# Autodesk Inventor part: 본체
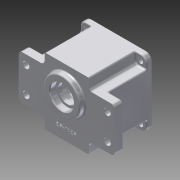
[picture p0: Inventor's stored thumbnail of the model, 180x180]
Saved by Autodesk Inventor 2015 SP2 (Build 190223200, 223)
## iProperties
Created: 2015-06
Part Number: 본체
Material: 알루미늄 6061
Document SubType Name: Modeling
Designer: AMC
Density: 2.7 g/cm^3
Appearance: 알루미늄 - 평지
Mass: 702.679 g
Surface Area: 673.039 cm^2
Volume: 260.252 cm^3
Author: AMC
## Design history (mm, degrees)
sketch "스케치1"
  geometry: L1 (-45, 45)-(45, 45); L2 (45, 45)-(45, -45); L3 (45, -45)-(-45, -45); L4 (-45, -45)-(-45, 45); 3 further points
  constraints: 8 end point, 2 midpoint, 2 parallel, 2 perpendicular, 1 horizontal, 1 horizontal alignment, 1 vertical alignment
  dimensions: "d0" = 90 distance of L1.start L1.end
extrude "돌출1" new body sketch "스케치1" distance "d1" = 70; taper "d2" = 0 deg
sketch "스케치2"
  geometry: L1 (-65, 30)-(65, 30); L2 (65, 30)-(65, -30); L3 (65, -30)-(-65, -30); L4 (-65, -30)-(-65, 30); 3 further points
  constraints: 8 end point, 2 midpoint, 2 parallel, 1 horizontal, 1 horizontal alignment, 1 perpendicular, 1 vertical alignment
  dimensions: "d3" = 60 distance of L3.end L1.start; "d4" = 130 distance of L1.start L1.end
extrude "돌출2" join sketch "스케치2" distance "d5" = 12; taper "d6" = 0 deg
sketch "스케치3"
  geometry: 2 further points
  constraints: 1 coincident
hole "구멍1" sketch "스케치3" at (0, 0) diameter "d7" = 78; stored, may be unused: countersink angle "d11" = 90 deg, drill point angle "d13" = 0 deg; dims "d8" = 6, "d9" = 80, "d10" = 9, "d12" = 61
sketch "스케치4"
  geometry: L1 (65, -30)-(45, -30) reference; L2 (45, -30)-(45, -45) reference; L3 (45, -45)-(-45, -45) reference; L4 (-45, -45)-(-45, -30) reference; L5 (-45, -30)-(-65, -30) reference; L6 (-65, -30)-(-65, 30) reference; L7 (-65, 30)-(-45, 30) reference; L8 (-45, 30)-(-45, 45) reference; L9 (-45, 45)-(45, 45) reference; L10 (45, 45)-(45, 30) reference; L11 (45, 30)-(65, 30) reference; L12 (65, 30)-(65, -30) reference; L13 (-45, 45)-(-30, 45); L14 (-30, 45)-(-30, 30); L15 (-30, 30)-(-45, 30); L16 (-45, 30)-(-45, 45); L17 (45, 45)-(30, 45); L18 (30, 45)-(30, 30); L19 (30, 30)-(45, 30); L20 (45, 30)-(45, 45); L21 (-45, -45)-(-30, -45); L22 (-30, -45)-(-30, -30); L23 (-30, -30)-(-45, -30); L24 (-45, -30)-(-45, -45); L25 (45, -45)-(30, -45); L26 (30, -45)-(30, -30); L27 (30, -30)-(45, -30); L28 (45, -30)-(45, -45); 1 further point
  constraints: 32 end point, 8 parallel, 5 equal length, 4 horizontal, 4 perpendicular
  dimensions: "d14" = 60 distance between parallel lines of L18 L14; "d15" = 60 distance between parallel lines of L23 L15; "d16" = 60 distance between parallel lines of L26 L22
extrude "돌출3" cut sketch "스케치4" distance "d17" = 63; taper "d18" = 0 deg
fillet "모깎기1" dims "d19" = 5
fillet "모깎기2" dims "d20" = 8
sketch "스케치5"
  geometry: C1 r 25 at (0, 11); 1 further point
  constraints: 1 centre point, 1 vertical alignment
  dimensions: "d21" = 11 distance of point (0, 0) C1.centre; "d22" = 50 diameter of C1
extrude "돌출4" join sketch "스케치5" distance "d23" = 7; taper "d24" = 0 deg
sketch "스케치6"
  geometry: C1 r 20.5 at (0, 11); C2 r 14 at (0, -20); 1 further point
  constraints: 2 centre point, 2 vertical alignment
  dimensions: "d25" = 11 distance of point (0, 0) C1.centre; "d26" = 20 distance of C2.centre point (0, 0); "d27" = 41 diameter of C1; "d28" = 28 diameter of C2
extrude "돌출5" join sketch "스케치6" distance "d29" = 7; taper "d30" = 0 deg
hole "구멍2" diameter "d33" = 25; stored, may be unused: countersink angle "d37" = 90 deg, drill point angle "d39" = 0 deg; dims "d31" = 10, "d32" = 10, "d34" = 6, "d35" = 32, "d36" = 8, "d38" = 61
hole "구멍3" diameter "d42" = 25; stored, may be unused: countersink angle "d46" = 90 deg, drill point angle "d48" = 0 deg; dims "d40" = 10, "d41" = 10, "d43" = 6, "d44" = 35, "d45" = 10, "d47" = 61
hole "구멍4" diameter "d51" = 19; stored, may be unused: countersink angle "d55" = 90 deg, drill point angle "d57" = 0 deg; dims "d49" = 10, "d50" = 10, "d52" = 6, "d53" = 22, "d54" = 7, "d56" = 8
fillet "모깎기3" dims "d58" = 2
fillet "모깎기4" dims "d59" = 2
fillet "모깎기5" dims "d60" = 2
fillet "모깎기8" dims "d63" = 2
fillet "모깎기9" dims "d64" = 2
fillet "모깎기10" dims "d65" = 2
fillet "모깎기11" dims "d66" = 2
chamfer "모따기1" distance "d67" = 1; stored, may be unused: second distance "d68" = 2, angle "d69" = 45 deg
chamfer "모따기2" distance "d70" = 1; stored, may be unused: second distance "d71" = 2, angle "d72" = 45 deg
fillet "모깎기12" dims "d73" = 2
sketch "스케치7"
  geometry: L1 (-28, 45)-(28, 45) reference; L2 (30, 43)-(30, 35) reference; L3 (35, 30)-(43, 30) reference; L4 (45, 28)-(45, -28) reference; L5 (43, -30)-(35, -30) reference; L6 (30, -35)-(30, -43) reference; L7 (28, -45)-(-28, -45) reference; L8 (-30, -43)-(-30, -35) reference; L9 (-35, -30)-(-43, -30) reference; L10 (-45, -28)-(-45, 28) reference; L11 (-43, 30)-(-35, 30) reference; L12 (-30, 35)-(-30, 43) reference; L13 (0, 0)-(-39, 0); L14 (0, 0)-(-24.749, 24.749); L15 (-27.577, 21.92)-(-30.26, 24.603); L16 (-21.92, 27.577)-(-24.603, 30.26); C1 r 40 at (0, 0) reference; A1 r 2 centre (-28, 43) between (-28, 45) and (-30, 43) reference; A2 r 2 centre (28, 43) between (30, 43) and (28, 45) reference; A3 r 5 centre (35, 35) between (30, 35) and (35, 30) reference; A4 r 2 centre (43, 28) between (45, 28) and (43, 30) reference; A5 r 2 centre (43, -28) between (43, -30) and (45, -28) reference; A6 r 5 centre (35, -35) between (35, -30) and (30, -35) reference; A7 r 2 centre (28, -43) between (28, -45) and (30, -43) reference; A8 r 2 centre (-28, -43) between (-30, -43) and (-28, -45) reference; A9 r 5 centre (-35, -35) between (-30, -35) and (-35, -30) reference; A10 r 2 centre (-43, -28) between (-45, -28) and (-43, -30) reference; A11 r 2 centre (-43, 28) between (-43, 30) and (-45, 28) reference; A12 r 5 centre (-35, 35) between (-35, 30) and (-30, 35) reference; A13 r 39 centre (0, 0) between (-39, 0) and (-30.26, 24.603) reference; A14 r 39 centre (0, 0) between (-39, 0) and (-30.26, 24.603) reference; A15 r 4 centre (-24.749, 24.749) between (-27.577, 21.92) and (-21.92, 27.577); 1 further point
  constraints: 8 end point, 8 point on circle, 2 parallel, 2 tangent, 1 centre point, 1 coincident, 1 horizontal
  dimensions: "d75" = 45 deg angle of L13 L14; "d76" = 35 distance of L13.start L14.end; "d77" = 8 diameter of A15
extrude "돌출6" join sketch "스케치7" stored distance "d78" = 7; taper "d79" = 0 deg
fillet "모깎기13" dims "d80" = 3.5
hole "구멍5" diameter "d83" = 3.459; stored, may be unused: countersink angle "d87" = 90 deg, drill point angle "d89" = 118 deg; dims "d84" = 12, "d85" = 22, "d86" = 7, "d88" = 15, "d120" = 10, "d121" = 10
fillet "모깎기14" dims "d93" = 2
fillet "모깎기15" dims "d94" = 2
fillet "모깎기16" dims "d95" = 2
fillet "모깎기17" dims "d96" = 2
fillet "모깎기18" dims "d97" = 2
hole "구멍6" diameter "d100" = 7; stored, may be unused: countersink angle "d104" = 90 deg, drill point angle "d106" = 118 deg; dims "d98" = 10, "d99" = 10, "d101" = 12, "d102" = 22, "d103" = 7, "d105" = 15
sketch "스케치8"
  geometry: L1 (55, 17.5)-(55, -17.5); 2 further points
  constraints: 2 end point, 1 horizontal alignment, 1 midpoint, 1 vertical, 1 vertical alignment
  dimensions: "d107" = 35 distance of L1.start L1.end; "d108" = 55 distance of point (0, 0) point (55, 0)
hole "구멍7" sketch "스케치8" at (55, 17.5), (55, -17.5) diameter "d109" = 9; stored, may be unused: countersink angle "d113" = 90 deg, drill point angle "d115" = 118 deg; dims "d110" = 12, "d111" = 22, "d112" = 7, "d114" = 15
sketch "스케치9"
  geometry: L1 (-28, -45)-(28, -45) reference; 2 further points
  constraints: 1 vertical alignment, 1 other
  dimensions: "d116" = 15 distance from line of L1 point (0, -30)
feature "엠보싱1" sketch "스케치9" dims "d7" = 78, "d9" = 80, "d10" = 9, "d12" = 61, "d117" = 0.5, "d118" = 0
fillet "모깎기19" dims "d119" = 0.3
node "솔리드1"
pattern_circular "원형 패턴1" dims "d91" = 360 deg
mirror "대칭1"
mirror "대칭2"
mirror "대칭3"
node "절단 모서리 투영1"
node "절단 모서리 투영2"
